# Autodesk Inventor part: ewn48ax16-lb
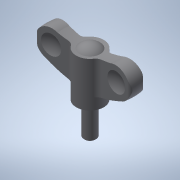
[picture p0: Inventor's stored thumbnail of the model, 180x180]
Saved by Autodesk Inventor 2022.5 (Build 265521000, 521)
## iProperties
Created: 2017-05
Part Number: ewn48ax16-lb
Material: 一般
Document SubType Name: Modeling
Designer: imaocorp
Density: 1 g/cm^3
Appearance: 既定
Author: imaocorp
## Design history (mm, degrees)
node "ewn48ax16-lb.x_t1"
node "ewn48ax16-lb"
node "Base1"
